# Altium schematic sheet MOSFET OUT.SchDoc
size A4; DocumentNumber: 11; SheetNumber: 11; SheetTotal: 11; PageSetup: Record=PageOptions¦CenterHorizontal=True¦CenterVertical=True¦PrintScale=0.97¦XCorrection=1.00¦YCorrection=1.00¦PrintKind=0¦BorderSize=5000000¦LeftOffset=5¦BottomOffset=0¦Orientation=1¦PaperLength=1000¦PaperWidth=1000¦Scale=100¦PaperSource=7¦PrintQuality=-4¦MediaType=1¦DitherType=10¦PaperKind=A4¦PrintScaleMode=1; Abteilung: Hard/Software Entwicklung
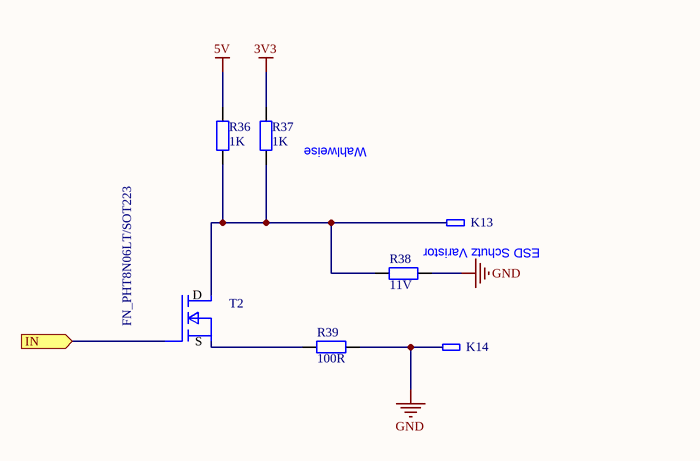
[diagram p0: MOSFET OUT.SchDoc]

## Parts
K13  WAGO-233  [KL02X0Y197A0]  (value not drawn)
K14  WAGO-233  [KL02X0Y197A0]  (value not drawn)
R36  1K  [RLCDT_1206]
R37  1K  [RLCDT_1206]
R38  11V  [RLCDT_1206]
R39  100R  [RLCDT_1206]
T2  FN_PHT8N06LT/SOT223  [SOT223]

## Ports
IN (in)

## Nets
3V3: R37.1
5V: R36.1
GND: K14.1 R38.1 R39.1
IN: T2.1(G) ; port IN
NetK13_1: K13.1 R36.2 R37.2 R38.2 T2.2(D)
NetR39_2: R39.2 T2.3(S)

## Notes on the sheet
- (near R37) Wahlweise
- ESD Schutz Varistor

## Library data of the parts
K13 K14 = WAGO-233: CAGE CLAMP RM2.5; B_Bestellnummer: 804769; D_Hersteller: WAGO; E_Herstellerbezeichnung: 233
R36 R37 R39 = R: Widerstand
R38 = R: Widerstand; D_Hersteller: WUERTH; E_Herstellerbezeichnung: 825 41 110
T2 = FN_PHT8N06LT/SOT223: DIGITAL N-CHAN POWER MOSFET 25V 0R6 0A95; B_Bestellnummer: 1081458; D_Hersteller: PHILLIPS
